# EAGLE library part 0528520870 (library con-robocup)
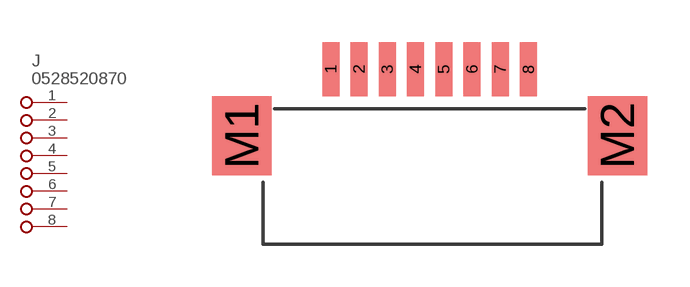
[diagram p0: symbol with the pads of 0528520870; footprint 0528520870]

Designator prefix J

## 0528520870  [0528520870]
1  1
2  2
3  3
4  4
5  5
6  6
7  7
8  8

## Footprint 0528520870 (pad centres in mm)
smd 0.6 x 1.9: 1 0,0; 2 1,0; 3 2,0; 4 3,0; 5 4,0; 6 5,0; 7 6,0; 8 7,0
smd 2.1 x 2.8: M1 -3.15,-2.35; M2 10.15,-2.35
